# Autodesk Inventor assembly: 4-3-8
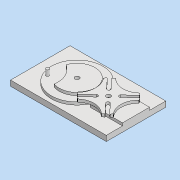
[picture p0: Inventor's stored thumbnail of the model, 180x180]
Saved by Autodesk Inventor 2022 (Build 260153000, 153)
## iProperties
Created: 2021-07
Part Number: 4-3-8
Document SubType Name: Assembly
Designer: DesignLab
Author: DesignLab
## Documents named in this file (4)
- d:\Users\DesignLab\Desktop\ver2022\ch04\4-3-8.iam
- d:\Users\DesignLab\Desktop\ver2022\ch04\03-ベース板_完成.ipt
- d:\Users\DesignLab\Desktop\ver2022\ch04\01-駆動車_完成.ipt
- d:\Users\DesignLab\Desktop\ver2022\ch04\02-従動車_完成.ipt
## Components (3 placed, 3 different names)
1. 03-ベース板_完成:1 — 回転:1, 回転:2
2. 01-駆動車_完成:1 — 回転:1
3. 02-従動車_完成:1 — 回転:2
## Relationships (2: RevoluteJoint 2)
- 回転:1 [RevoluteJoint]: 03-ベース板_完成:1 ↔ 01-駆動車_完成:1
- 回転:2 [RevoluteJoint]: 03-ベース板_完成:1 ↔ 02-従動車_完成:1
